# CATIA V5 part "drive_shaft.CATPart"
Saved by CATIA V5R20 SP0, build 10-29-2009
Part number: DriveShaft
Bounding box of the stored display mesh (mm): x -75 to 75, y -74.904 to 74.904, z 0 to 164
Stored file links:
  D:\OneDrive\OneDrive - 한양대학교\문서\Teaching\2021\CAD\Final Exam\oscillation motion\drive_shaft.CATPart
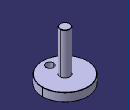
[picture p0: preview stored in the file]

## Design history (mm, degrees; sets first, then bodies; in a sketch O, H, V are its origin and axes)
Body1 (main body)
  Sketch1 on xy-plane, origin (0, 0, 0), H (1, 0, 0), V (0, 1, 0)
    circle A1 centre (0, 0) radius 75
    circle A2 centre (0, -50) radius 12.5
    point P1 (0, -50)
    radius A1 = 75
    radius A2 = 12.5
    distance P1 O = 50
    coincidence: P1 V
  Pad1: profile Sketch1, direction (0, 0, 1), length 28
  Sketch2 on end face of Pad1, origin (0, 0, 28), H (1, 0, 0), V (0, 1, 0)
    circle A1 centre (0, 0) radius 16
    radius A1 = 16
  Pad2: profile Sketch2, direction (0, 0, 1), length 136
  Chamfer1: length 1, angle 45, on edge [face of Pad2 from Sketch2.A1 | end face of Pad2]; edge [face of Pad1 from Sketch1.A1 | end face of Pad1]; edge [start face of Pad1 | face of Pad1 from Sketch1.A1]
  Plane1: type Offset, RefPlane zx-plane, Offset 20, reversed
  Sketch3 on Plane1, origin (0, -20, 0), H (-1, 0, 0), V (0, 0, 1)
    arc A1 centre (0, 146) radius 5 from (5, 146) to (-5, 146) ccw
    point P1 (0, 146)
    arc A2 centre (0, 120) radius 5 from (-5, 120) to (5, 120) ccw
    line L1 (-5, 146) -> (-5, 120)
    line L2 (5, 146) -> (5, 120)
    point P4 (5, 120)
    point P6 (5, 120)
    reference projected line E1 (-15, 164) -> (15, 164) from edge [face of Chamfer1 | end face of Pad2]
    radius A1 = 5
    distance A1 A2 = 36
    distance P1 E1 = 18
    tangency: L1 A1, L2 A1, L2 A2, L1 A2
    vertical: L2 V
    coincidence: L2 P6, V P1, P4 P6
  Pocket1: profile Sketch3, direction (0, 1, 0), length 8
